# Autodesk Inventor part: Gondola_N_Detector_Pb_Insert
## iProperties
Shininess: 64.0
Length Units: 11272
Angle Units: 11279
Time Units: 11290
Mass Units: 11286
Length Display Precision: 3
Angle Display Precision: 2
Compacted: True
Part Number: Gondola_N_Detector_Pb_Insert
Document SubType Name: Modeling
Created: 2004-12
Designer: John Blackburn
Material: Lead
Manufacturer: Standard
Standards Organization: Custom
Density: 0.0
Volumn: 0.0
Area: 0.0
PropertySet Name: Model Information
Control State: 0
Master: False
Checked Out: False
Author: John Blackburn
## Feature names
1. Extrusion1
2. Extrusion2
